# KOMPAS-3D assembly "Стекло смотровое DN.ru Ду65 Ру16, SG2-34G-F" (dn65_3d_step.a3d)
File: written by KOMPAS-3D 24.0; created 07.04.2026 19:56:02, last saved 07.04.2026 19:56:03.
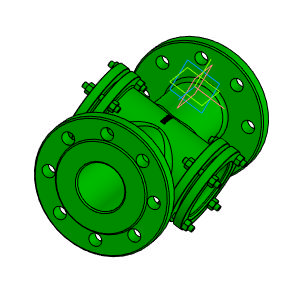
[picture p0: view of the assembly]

Document properties: Автор: Main; Полное имя файла: D:\DN.ru Аутсерс\Стекло смотровое DN.ru\Исходники\Стекло смотровое DN.ru SG2-34G-F тип В ГОСТ 21836-2021 Ду65 Ру16, углеродистая сталь, фланцевое\dn65_3d_step.a3d

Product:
- Component [detail]: Деталь  | qty 1  | pos. 1  | Масса: 12.292251; Автор: Main; source file: ДетальДеталь.m3d
- Component [detail]: Стекло  | qty 2  | pos. 2  | Масса: 0.331901; Автор: Main; source file: СтеклоСтекло.m3d
- Component [detail]: ANSI B18.2.4.2M - M8x1,25 - 13  | designation ANSI B18.2.4.2M - M8x1,25  | qty 1  | pos. 3  | Масса: 0.006562; Автор: Main; source file: ANSI B18.2.4.2M - M8x1,25ANSI B18.2.4.2M - M8x1,25 - 13.m3d
- Component [detail]: ANSI B18.2.4.2M - M8x1,25 - 13  | designation ANSI B18.2.4.2M - M8x1,25  | qty 15  | pos. 3  | Масса: 0.006562; Комментарий: Типы метрических   шестигранных гаек   2; Автор: Main; additional columns: Сталь, мягкая; source file: ANSI B18.2.4.2M - M8x1,25ANSI B18.2.4.2M - M8x1,25 - 13.m3d
- Part/product: Стекло смотровое DN.ru Ду65 Ру16  | designation SG2-34G-F
    Масса: 14
    Раздел спецификации: Прочие изделия
    Примечание: D500-00085

Expressions: SG2-34G-F
Referenced files in D:\DN.ru Аутсерс\Стекло смотровое DN.ru\Исходники\Стекло смотровое DN.ru SG2-34G-F тип В ГОСТ 21836-2021 Ду65 Ру16, углеродистая сталь, фланцевое\: ДетальДеталь.m3d, СтеклоСтекло.m3d, ANSI B18.2.4.2M - M8x1,25ANSI B18.2.4.2M - M8x1,25 - 13.m3d
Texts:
  Стекло Стекло (1)
  Стекло Стекло (2)
  ANSI B18.2.4.2M - M8x1,25 ANSI B18.2.4.2M - M8x1,25 - 13 (1)
  ANSI B18.2.4.2M - M8x1,25 ANSI B18.2.4.2M - M8x1,25 - 13 (2)
  ANSI B18.2.4.2M - M8x1,25 ANSI B18.2.4.2M - M8x1,25 - 13 (3)
  ANSI B18.2.4.2M - M8x1,25 ANSI B18.2.4.2M - M8x1,25 - 13 (4)
  ANSI B18.2.4.2M - M8x1,25 ANSI B18.2.4.2M - M8x1,25 - 13 (5)
  ANSI B18.2.4.2M - M8x1,25 ANSI B18.2.4.2M - M8x1,25 - 13 (6)
  ANSI B18.2.4.2M - M8x1,25 ANSI B18.2.4.2M - M8x1,25 - 13 (7)
  ANSI B18.2.4.2M - M8x1,25 ANSI B18.2.4.2M - M8x1,25 - 13 (8)
  ANSI B18.2.4.2M - M8x1,25 ANSI B18.2.4.2M - M8x1,25 - 13 (9)
  ANSI B18.2.4.2M - M8x1,25 ANSI B18.2.4.2M - M8x1,25 - 13 (10)
  ANSI B18.2.4.2M - M8x1,25 ANSI B18.2.4.2M - M8x1,25 - 13 (11)
  ANSI B18.2.4.2M - M8x1,25 ANSI B18.2.4.2M - M8x1,25 - 13 (12)
  ANSI B18.2.4.2M - M8x1,25 ANSI B18.2.4.2M - M8x1,25 - 13 (13)
  ANSI B18.2.4.2M - M8x1,25 ANSI B18.2.4.2M - M8x1,25 - 13 (14)
  ANSI B18.2.4.2M - M8x1,25 ANSI B18.2.4.2M - M8x1,25 - 13 (15)
  ANSI B18.2.4.2M - M8x1,25 ANSI B18.2.4.2M - M8x1,25 - 13 (16)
